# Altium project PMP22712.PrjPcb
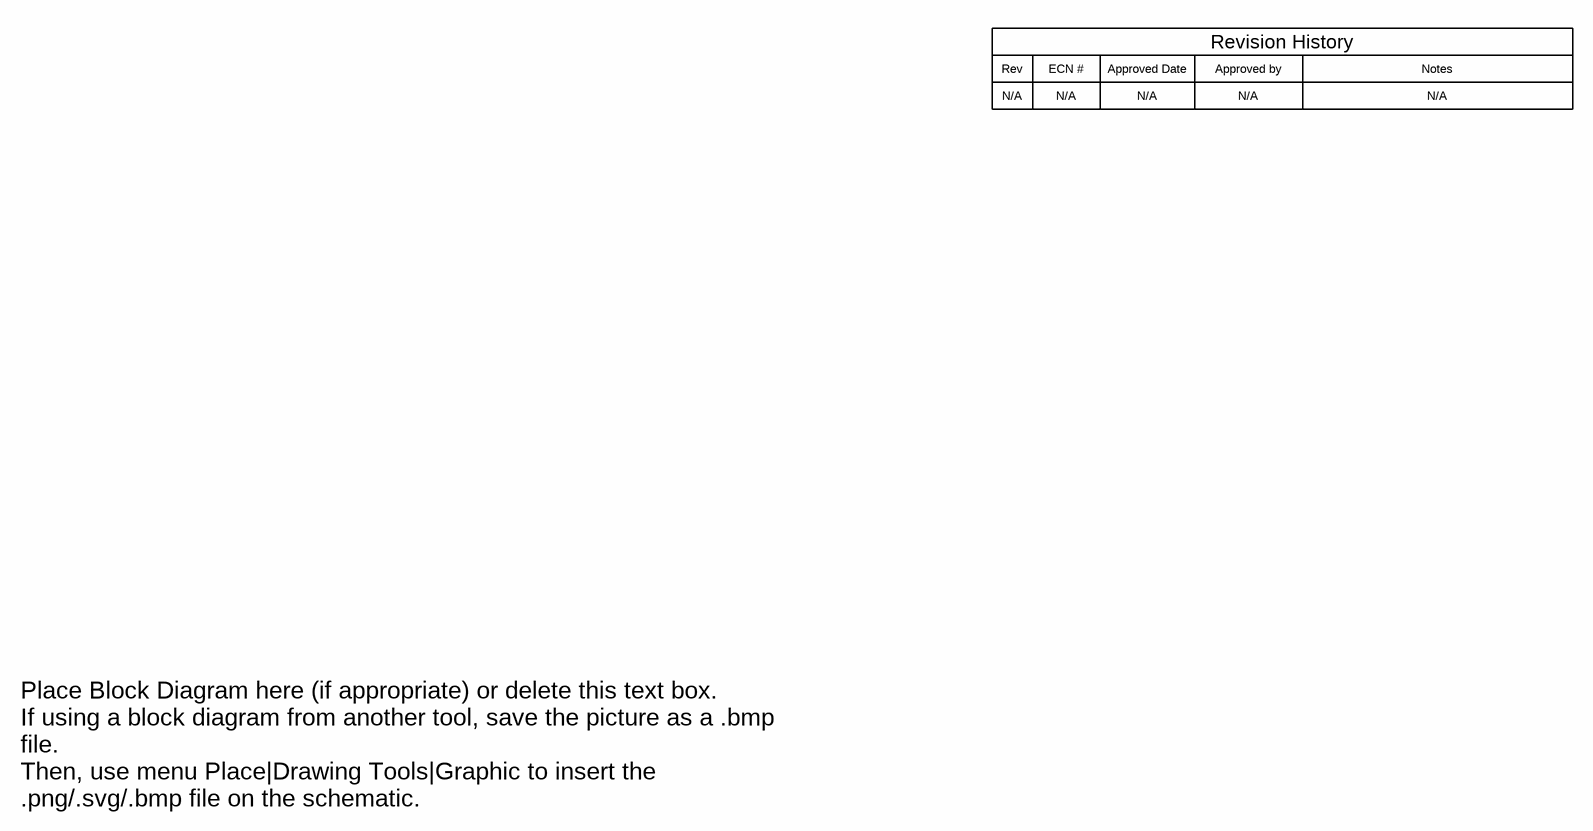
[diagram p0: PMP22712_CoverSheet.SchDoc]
TID: N/A; TechSupport: http://www.ti.com/support; SCH_Rev: E2; PRJ_Title: Automotive Gate Drive Supply Daughter Card; PRJ_Number: PMP22712; PRJ_Engineer: B McDonald; PRJ_Customer: Public Release; PCB_Rev: E2; CopyrightYear: 2020
3 sheets, 31 parts. Net scope: global (net labels, ports and power ports of the same name join across sheets).
Board file: PMP22712_PCB.PcbDoc
Sheets:
  PMP22712_CoverSheet.SchDoc
  PMP22712_Main.SchDoc
  PMP22712_Hardware.SchDoc

## Sheet PMP22712_CoverSheet.SchDoc
size 431 x 279 mm; Date: Not shown in title block; ApprovedBy: Not shown in title block; CheckedBy: Not shown in title block; Author: Not shown in title block; CompanyName: Not shown in title block; Engineer: Not shown in title block; Organization: Not shown in title block; Address1: Not shown in title block; Address2: Not shown in title block; Address3: Not shown in title block; Address4: Not shown in title block; DocumentNumber: 1; Revision: Use project parameter SCH_Rev; SheetNumber: 1; SheetTotal: 3; PageSetup: Record=PageOptions¦CenterHorizontal=True¦CenterVertical=True¦PrintScale=1.00¦XCorrection=1.00¦YCorrection=1.00¦PrintKind=0¦BorderSize=5000000¦LeftOffset=0¦BottomOffset=0¦Orientation=2¦PaperLength=1000¦PaperWidth=1000¦Scale=100¦PaperSource=15¦PrintQuality=600¦MediaType=1¦DitherType=10¦PaperKind=Letter¦PrintScaleMode=1

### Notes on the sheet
- Rev
- N/A
- ECN #
- Approved Date
- Approved by
- Revision History
- Notes
- Place Block Diagram here (if appropriate) or delete this text box.
  If using a block diagram from another tool, save the picture as a .bmp file.
  Then, use menu Place|Drawing Tools|Graphic to insert the .png/.svg/.bmp file on the schematic.

## Sheet PMP22712_Main.SchDoc
size A3; Date: Not shown in title block; ApprovedBy: Not shown in title block; CheckedBy: Not shown in title block; Author: Not shown in title block; CompanyName: Not shown in title block; Engineer: Not shown in title block; Organization: Not shown in title block; Address1: Not shown in title block; Address2: Not shown in title block; Address3: Not shown in title block; Address4: Not shown in title block; DocumentNumber: 2; Revision: Use project parameter SCH_Rev; SheetNumber: 2; SheetTotal: 3; PageSetup: Record=PageOptions¦CenterHorizontal=True¦CenterVertical=True¦PrintScale=1.00¦XCorrection=1.00¦YCorrection=1.00¦PrintKind=0¦BorderSize=5000000¦LeftOffset=0¦BottomOffset=0¦Orientation=2¦PaperLength=1000¦PaperWidth=1000¦Scale=100¦PaperSource=15¦PrintQuality=600¦MediaType=1¦DitherType=10¦PaperKind=Letter¦PrintScaleMode=1
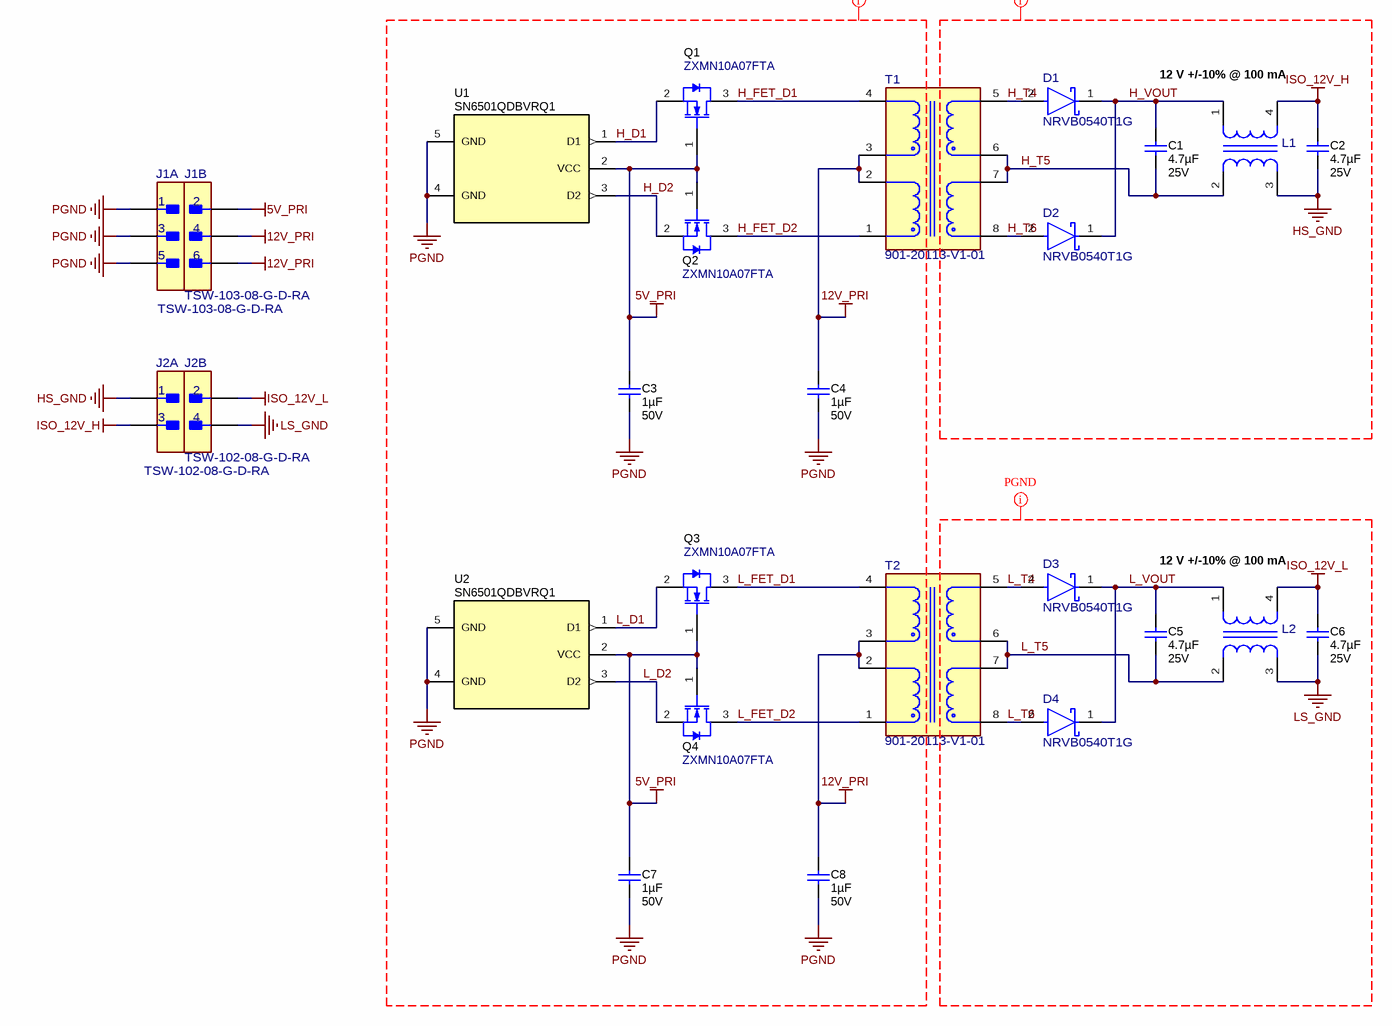
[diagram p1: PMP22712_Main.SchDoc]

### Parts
C1  Cap_F: 4.7µF  VDC_V: 25V  [0805_HV]  (hidden comment: GRM21BR71E475KA73L)
C2  Cap_F: 4.7µF  VDC_V: 25V  [0805_HV]  (hidden comment: GRM21BR71E475KA73L)
C3  Cap_F: 1µF  VDC_V: 50V  [0603]  (hidden comment: UMK107AB7105KA-T)
C4  Cap_F: 1µF  VDC_V: 50V  [0603]  (hidden comment: UMK107AB7105KA-T)
C5  Cap_F: 4.7µF  VDC_V: 25V  [0805_HV]  (hidden comment: GRM21BR71E475KA73L)
C6  Cap_F: 4.7µF  VDC_V: 25V  [0805_HV]  (hidden comment: GRM21BR71E475KA73L)
C7  Cap_F: 1µF  VDC_V: 50V  [0603]  (hidden comment: UMK107AB7105KA-T)
C8  Cap_F: 1µF  VDC_V: 50V  [0603]  (hidden comment: UMK107AB7105KA-T)
D1  NRVB0540T1G  [FP-NRVB0540T1G_SOD-123-MFG]
D2  NRVB0540T1G  [FP-NRVB0540T1G_SOD-123-MFG]
D3  NRVB0540T1G  [FP-NRVB0540T1G_SOD-123-MFG]
D4  NRVB0540T1G  [FP-NRVB0540T1G_SOD-123-MFG]
J1  TSW-103-08-G-D-RA  [FP-TSW-103-08-G-D-RA_HDR6-MFG]  (parts A,B of 2)
J2  TSW-102-08-G-D-RA  [FP-TSW-102-08-G-D-RA_HDR4-MFG]  (parts A,B of 2)
L1  ACM2012-900-2P-T001  [FP-ACM2012-900-2P-T001_SMD4-MFG]  (value not drawn)
L2  ACM2012-900-2P-T001  [FP-ACM2012-900-2P-T001_SMD4-MFG]  (value not drawn)
Q1  ZXMN10A07FTA  [SOT-23]
Q2  ZXMN10A07FTA  [SOT-23]
Q3  ZXMN10A07FTA  [SOT-23]
Q4  ZXMN10A07FTA  [SOT-23]
T1  901-20113-V1-01  [FP-901-20113-V1-01_SMT_XFRMR_9MM54_10MM26-MFG]
T2  901-20113-V1-01  [FP-901-20113-V1-01_SMT_XFRMR_9MM54_10MM26-MFG]
U1  SN6501QDBVRQ1  [DBV0005A_L]
U2  SN6501QDBVRQ1  [DBV0005A_L]

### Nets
5V_PRI: C3.1 C7.1 J1.2 Q1.1(G) Q2.1(G) Q3.1(G) Q4.1(G) U1.2(VCC) U2.2(VCC)
12V_PRI: C4.1 C8.1 J1.4 J1.6 T1.2 T1.3 T2.2 T2.3
HS_GND: C2.2 J2.1 L1.3
ISO_12V_H: C2.1 J2.3 L1.4
ISO_12V_L: C6.1 J2.2 L2.4
LS_GND: C6.2 J2.4 L2.3
PGND: C3.2 C4.2 C7.2 C8.2 J1.1 J1.3 J1.5 U1.4(GND) U1.5(GND) U2.4(GND) U2.5(GND)
H_D1: Q1.2(S) U1.1(D1)
H_D2: Q2.2(S) U1.3(D2)
H_FET_D1: Q1.3(D) T1.4
H_FET_D2: Q2.3(D) T1.1
H_T4: D1.2(ANODE) T1.5
H_T5: C1.2 L1.2 T1.6 T1.7
H_T6: D2.2(ANODE) T1.8
H_VOUT: C1.1 D1.1(CATHODE) D2.1(CATHODE) L1.1
L_D1: Q3.2(S) U2.1(D1)
L_D2: Q4.2(S) U2.3(D2)
L_FET_D1: Q3.3(D) T2.4
L_FET_D2: Q4.3(D) T2.1
L_T4: D3.2(ANODE) T2.5
L_T5: C5.2 L2.2 T2.6 T2.7
L_T6: D4.2(ANODE) T2.8
L_VOUT: C5.1 D3.1(CATHODE) D4.1(CATHODE) L2.1

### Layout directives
net class VSWNET: H_T4, H_T5, H_T6, H_VOUT, HS_GND, ISO_12V_H
net class INGND: 5V_PRI, 12V_PRI, H_D1, H_D2, H_FET_D1, H_FET_D2, L_D1, L_D2, L_FET_D1, L_FET_D2, PGND
net class PGND: ISO_12V_L, L_T4, L_T5, L_T6, L_VOUT, LS_GND

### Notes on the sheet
- 12 V +/-10% @ 100 mA

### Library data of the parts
C1 C2 C5 C6 = CMP-0008346-2: CAP, CERM, 4.7 uF, 25 V, +/- 10%, X7R, 0805; Manufacturer: MuRata; TaMin_C: -55°C; Polarized: N; SizeAreaWB_mm2: 6.75; Value1: Unknown; U/M: EA; Value: 4.7uF; TaMax_C: 125°C; SizeZ_mm: 1.45; SizeX_mm: 2; SizeY_mm: 1.25; Cap_Case: 0805; SizeArea_mm2: 2.5; AEC Category: Q200
C3 C4 C7 C8 = CMP-0007508-5: CAP, CERM, 1 uF, 50 V, +/- 10%, X7R, 0603; Manufacturer: Taiyo Yuden; TaMin_C: -55°C; Polarized: N; SizeAreaWB_mm2: 4.68; Value1: Unknown; U/M: EA; Value: 1uF; TaMax_C: 125°C; SizeZ_mm: 1; SizeX_mm: 1.6; SizeY_mm: 0.8; SizeArea_mm2: 1.28; AEC Category: Q200
D1-D4 = CMP-0090564-1: Diode Schottky 40V 500mA Surface Mount SOD-123; Manufacturer: On Semiconductor; Max Surge Forward Current: 5.5A; Standoff Height: 0mm; Import Ts: 1521847448; AEC Grade: Grade 0; AEC Qualified: Yes; Peak Reverse Current: 20uA; SizeZ_mm: 1.35mm; TJmax_C: 150°C; Ciiva Ids: 822523; Forward Current: 0.5A
J1 = CMP-0090622-1: Connector Header Through Hole, Right Angle 6 position 0.100" (2.54mm); Manufacturer: Samtec; ContactFinish: Gold,Nickel; Current_A: 5.7A; Is Female: no; SizeZ_mm: 5.69mm; Voltage_V: 550V; Row_Count: 2; Conn Gender: Male
J2 = CMP-0088304-1: CONN HEADER R/A 4POS 2.54MM; Manufacturer: Samtec; SizeZ_mm: 5.69mm; Row_Count: 2; ContactFinish: Gold,Tin; AEC Qualified: No; Conn Gender: Male; Conn Orientation: Right Angle
L1 L2 = CMP-0090488-1: 2 Line Common Mode Choke Surface Mount 90 Ohms @ 100MHz 400mA DCR 190mOhm; Manufacturer: TDK; SizeZ_mm: 1.3mm; DCR_ohm: 0.19; AEC Qualified: Yes; AEC Grade: Grade 2; Impedance At Frequency: 90Ω @ 100MHz
Q1-Q4 = CMP-0001041-3: MOSFET, N-CH, 100 V, 0.7 A, AEC-Q101, SOT-23; Alternate Manufacturer: None; Manufacturer: Diodes Inc.; SizeZ_mm: 1.1; ChType: N; Value2: 2.9 nC; VdsMax_V: 100V; SizeX_mm: 2.5; SizeY_mm: 3; Vgs_V: 20V; QgTyp_nC: 2.9; AEC Qualified: Y; Value: 100V; SizeArea_mm2: 7.5; AEC Category: Q101; IdsMax_A: 700mA; SizeAreaWB_mm2: 14; U/M: EA
T1 T2 = CMP-0090597-1: Automotive Transformer, 1:1, 80uH, 3500VAC, SMT, 9.54x10.26x5.38; Manufacturer: Wurth Electronics; DCR_ohm: 0.25; Voltage_Isolation_Vrms: 3.5kV; SizeZ_mm: 5.38mm; AEC Qualified: Yes; Ind_H: 80µH; Frequency_Fixed: 300-620kHz
U1 U2 = CMP-0076093-1: Automotive Low-Noise 350 mA, 410 kHz Transformer Driver, DBV0005A (SOT-23-5); Manufacturer: Texas Instruments; SizeAreaWB_mm2: 14.82; SizeArea_mm2: 8.12; SizeZ_mm: 1.45; SizeY_mm: 2.9; U/M: EA; CompType: IC; SizeX_mm: 2.8

## Sheet PMP22712_Hardware.SchDoc
size 431 x 279 mm; Date: Not shown in title block; ApprovedBy: Not shown in title block; CheckedBy: Not shown in title block; Author: Not shown in title block; CompanyName: Not shown in title block; Engineer: Not shown in title block; Organization: Not shown in title block; Address1: Not shown in title block; Address2: Not shown in title block; Address3: Not shown in title block; Address4: Not shown in title block; DocumentNumber: 3; Revision: Use project parameter SCH_Rev; SheetNumber: 3; SheetTotal: 3; PageSetup: Record=PageOptions¦CenterHorizontal=True¦CenterVertical=True¦PrintScale=1.00¦XCorrection=1.00¦YCorrection=1.00¦PrintKind=0¦BorderSize=5000000¦LeftOffset=0¦BottomOffset=0¦Orientation=2¦PaperLength=1000¦PaperWidth=1000¦Scale=100¦PaperSource=15¦PrintQuality=600¦MediaType=1¦DitherType=10¦PaperKind=Letter¦PrintScaleMode=1
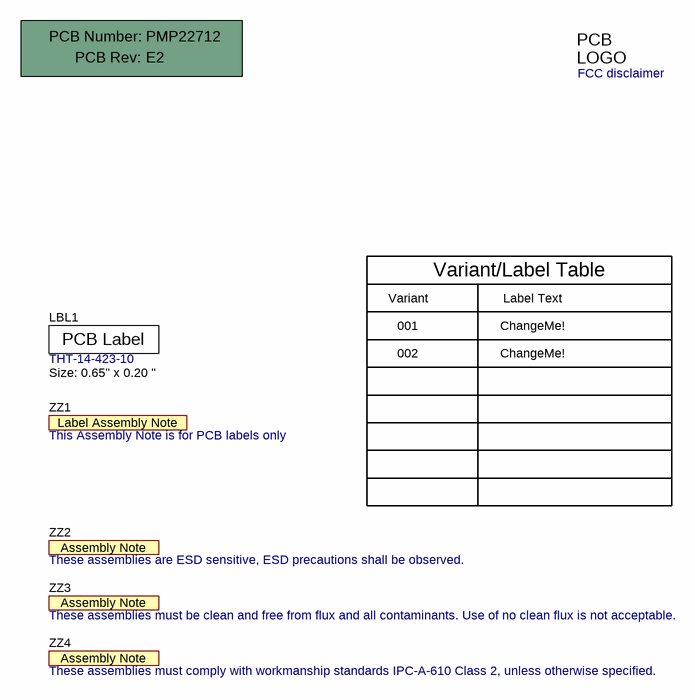
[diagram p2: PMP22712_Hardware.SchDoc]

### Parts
!PCB1  Printed Circuit Board  (value not drawn)  (mechanical)
LBL1  THT-14-423-10  Note: Size: 0.65" x 0.20 "  [Label_650x200]
Logo3  FCC disclaimer  [FCC_disclaimer]  (no BOM)
ZZ1  This Assembly Note is for PCB labels only  [AssemblyNoteLabel]  (no BOM)
ZZ2  These assemblies are ESD sensitive, ESD precautions shall be observed.  [AssemblyNote]  (no BOM)
ZZ3  These assemblies must be clean and free from flux and all contaminants. Use of no clean flux is not acceptable.  [AssemblyNote]  (no BOM)
ZZ4  These assemblies must comply with workmanship standards IPC-A-610 Class 2, unless otherwise specified.  [AssemblyNote]  (no BOM)

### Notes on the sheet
- Variant
- Variant/Label Table
- Label Text
- 001
- 002
- ChangeMe!

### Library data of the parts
!PCB1 = CMP-0003618-2: Manufacturer: Any; PartNumber: PMP22712
LBL1 = CMP-0003625-1: Thermal Transfer Printable Labels, 0.650" W x 0.200" H - 10,000 per roll; Manufacturer: Brady
Logo3 = CMP-0074847-1: FCC_disclaimer
ZZ1 = CMP-0003616-3
ZZ2 = CMP-0077236-1
ZZ3 = CMP-0077237-1
ZZ4 = CMP-0077238-1

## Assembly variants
001: not fitted FID1 FID2 FID3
